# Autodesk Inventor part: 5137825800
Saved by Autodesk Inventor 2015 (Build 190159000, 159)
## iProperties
Created: 2020-07
Part Number: 5137825800
Checked By: TraceParts S.A.
Material: Generic
Catalog Web Link: www.traceparts.com
Document SubType Name: Modeling
Designer: TraceParts
Density: 1 g/cm^3
Appearance: Default
Company: TraceParts S.A.
Author: TraceParts
REFERENCE: 5137825800
DESIGN: CVAB/4-9000/500 N D 1,29KW (230V) 50HZ - 5137825800
SUPPLIER: Soler & Palau
TraceParts.PartNumber: 10-14122018-105188
TraceParts.PartTitle: CVAT-N
TraceParts.InstanceId: 10-14122018-1051884Y2O1BIOD4XGAV7MNSJE52LI8
TraceParts.PartStatus: Published
TraceParts.PartVersion: 1.0.4
TRACEPARTS: TRACEPARTS
TraceParts.PartLanguage: en
TraceParts.ClassPath: SOLER_PALAU:10-14122018-105188
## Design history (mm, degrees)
feature "5137825800"
body "Solid1"
